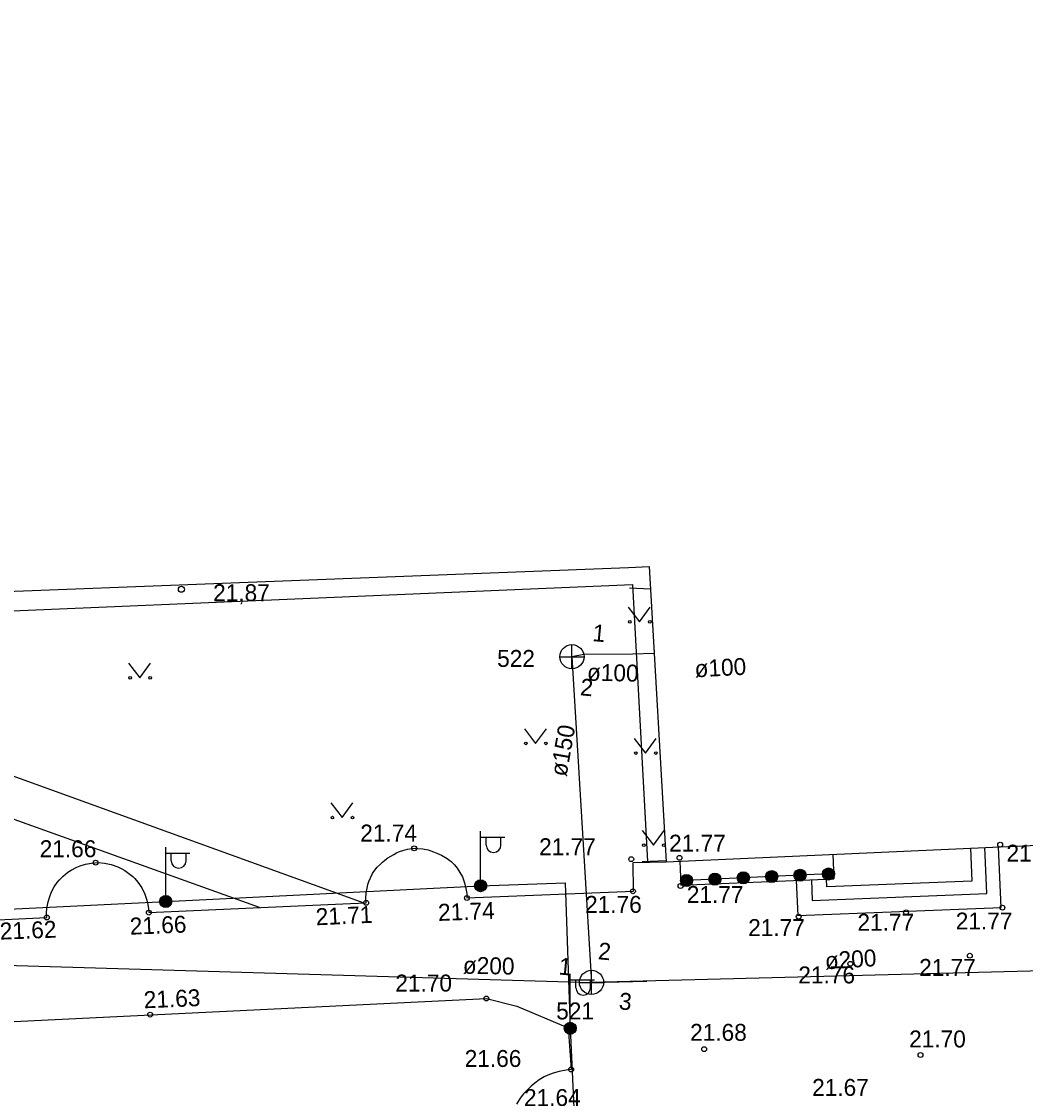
# Model space of a CAD drawing. Extents: x 714038 to 714279, y 6589845 to 6590041.
# Drawn here: x 714195.16 to 714236.66, y 6589955.84 to 6590000.35 of the extents above; entities that cross this region are included whole.
import ezdxf

# ---------------------------------------------------------------- set-up
doc = ezdxf.new("R2010")
doc.units = 0
for name, color, linetype in [('HALJASTUS', 7, 'Continuous'), ('HOONE', 7, 'Continuous'), ('HOONEDET', 7, 'Continuous'), ('KKAEV', 7, 'Continuous'), ('KORGUS', 7, 'Continuous'), ('KTRASS', 7, 'Continuous'), ('MPKAABEL', 7, 'Continuous'), ('POST', 7, 'Continuous'), ('RAJATIS', 7, 'Continuous'), ('SIKAEV', 7, 'Continuous'), ('TEE', 7, 'Continuous'), ('TORU NR', 7, 'Continuous')]:
    doc.layers.add(name, color=color, linetype=linetype)

msp = doc.modelspace()

# ---------------------------------------------------------------- linework, layer by layer
at = {"layer": 'HALJASTUS'}
for p, q in [((714220.237, 6589976.147), (714220.7, 6589975.54)), ((714220.7, 6589975.54), (714221.146, 6589976.147)), ((714199.587, 6589973.837), (714200.05, 6589973.23)), ((714200.05, 6589973.23), (714200.496, 6589973.837)), ((714215.947, 6589971.127), (714216.41, 6589970.52)), ((714216.41, 6589970.52), (714216.856, 6589971.127)), ((714220.487, 6589970.727), (714220.95, 6589970.12)), ((714220.95, 6589970.12), (714221.396, 6589970.727)), ((714207.947, 6589968.057), (714208.41, 6589967.45)), ((714208.41, 6589967.45), (714208.856, 6589968.057)), ((714220.817, 6589966.917), (714221.28, 6589966.31)), ((714221.28, 6589966.31), (714221.726, 6589966.917))]:
    msp.add_line(p, q, dxfattribs=at)
for centre in [(714220.299, 6589975.54), (714221.128, 6589975.54), (714199.649, 6589973.23), (714200.478, 6589973.23), (714216.009, 6589970.52), (714216.838, 6589970.52), (714220.549, 6589970.12), (714221.378, 6589970.12), (714208.009, 6589967.45), (714208.838, 6589967.45), (714220.879, 6589966.31), (714221.708, 6589966.31)]:
    msp.add_circle(centre, 0.055, dxfattribs=at)
at = {"layer": 'HOONE'}
msp.add_lwpolyline([(714174.151, 6590040.965), (714175.285, 6590011.657), (714176.665, 6589976.107), (714220.25, 6589977.79), (714221.11, 6589977.83), (714221.8, 6589965.63), (714240.53, 6589966.47), (714239.93, 6589984.45), (714258.589, 6589985.264), (714256.524, 6590035.954)], dxfattribs=at)
at = {"layer": 'HOONEDET'}
for points in [[(714178.211, 6589976.159), (714178.235, 6589975.468), (714180.826, 6589975.404), (714220.421, 6589977.091), (714221.034, 6589965.634)], [(714220.29, 6589976.95), (714221.16, 6589976.9)], [(714235.647, 6589963.73), (714235.543, 6589966.246)], [(714227.807, 6589964.884), (714227.843, 6589964.02), (714235.053, 6589964.31), (714234.974, 6589966.221)], [(714234.387, 6589966.194), (714234.443, 6589964.83), (714228.447, 6589964.589), (714228.434, 6589964.91)], [(714228.699, 6589965.939), (714228.734, 6589964.922)], [(714222.364, 6589965.655), (714222.417, 6589964.66)], [(714222.417, 6589964.66), (714228.734, 6589964.922)], [(714227.181, 6589964.858), (714227.242, 6589963.4)], [(714227.242, 6589963.4), (714235.647, 6589963.73)]]:
    msp.add_lwpolyline(points, dxfattribs=at)
at = {"layer": 'KKAEV'}
for p, q in [((714217.91, 6589973.6), (714217.91, 6589974.6)), ((714217.41, 6589974.1), (714218.41, 6589974.1)), ((714218.72, 6589960.14), (714218.72, 6589961.14)), ((714218.22, 6589960.64), (714219.22, 6589960.64))]:
    msp.add_line(p, q, dxfattribs=at)
for centre in [(714217.91, 6589974.1), (714218.72, 6589960.64)]:
    msp.add_circle(centre, 0.5, dxfattribs=at)
at = {"layer": 'KORGUS'}
for centre, radius in [((714201.77, 6589976.89), 0.125), ((714211.39, 6589966.18), 0.1), ((714235.61, 6589966.331), 0.1), ((714220.363, 6589965.731), 0.1), ((714222.357, 6589965.787), 0.1), ((714198.227, 6589965.587), 0.1), ((714220.433, 6589964.407), 0.1), ((714222.398, 6589964.623), 0.1), ((714209.405, 6589963.927), 0.1), ((714213.572, 6589964.13), 0.1), ((714200.424, 6589963.524), 0.1), ((714231.721, 6589963.535), 0.1), ((714235.703, 6589963.728), 0.1), ((714196.207, 6589963.323), 0.1), ((714227.284, 6589963.357), 0.1), ((714234.358, 6589961.743), 0.1), ((714229.418, 6589961.405), 0.1), ((714214.375, 6589959.974), 0.1), ((714200.481, 6589959.309), 0.1), ((714223.379, 6589957.881), 0.1), ((714232.316, 6589957.64), 0.1), ((714217.882, 6589957.042), 0.1)]:
    msp.add_circle(centre, radius, dxfattribs=at)
at = {"layer": 'KTRASS'}
for points in [[(714220.41, 6589974.2), (714218.4, 6589974.19), (714217.91, 6589974.1)], [(714217.91, 6589974.1), (714218.72, 6589960.64)], [(714221.31, 6589974.24), (714220.41, 6589974.2)], [(714172.57, 6589962.002), (714218.72, 6589960.64)], [(714246.982, 6589961.372), (714218.72, 6589960.64)], [(714218.72, 6589960.64), (714221.01, 6589960.69)]]:
    msp.add_lwpolyline(points, dxfattribs=at)
at = {"layer": 'MPKAABEL'}
msp.add_lwpolyline([(714167.029, 6589999.261), (714167.805, 6589985.535), (714167.801, 6589985.524), (714168.701, 6589969.69), (714168.856, 6589964.517), (714181.003, 6589963.765), (714182.873, 6589963.649), (714187.834, 6589963.342), (714201.122, 6589963.986), (714214.138, 6589964.636), (714217.634, 6589964.759), (714217.843, 6589958.743), (714218.335, 6589947.958), (714218.782, 6589937.076), (714219.871, 6589937.206), (714226.57, 6589937.936), (714228.214, 6589938.132), (714236.763, 6589938.683), (714246.845, 6589940.926), (714247.938, 6589921.303)], dxfattribs=at)
at = {"layer": 'POST'}
for p, q in [((714214.138, 6589964.886), (714214.138, 6589966.886)), ((714201.122, 6589964.236), (714201.122, 6589966.236)), ((714214.138, 6589966.636), (714215.138, 6589966.636)), ((714214.365, 6589966.315), (714214.365, 6589966.636)), ((714214.977, 6589966.315), (714214.977, 6589966.636)), ((714201.122, 6589965.986), (714202.122, 6589965.986)), ((714201.349, 6589965.665), (714201.349, 6589965.986)), ((714201.961, 6589965.665), (714201.961, 6589965.986)), ((714217.843, 6589958.993), (714217.843, 6589960.993)), ((714217.843, 6589960.743), (714218.843, 6589960.743)), ((714218.07, 6589960.422), (714218.07, 6589960.743)), ((714218.682, 6589960.422), (714218.682, 6589960.743))]:
    msp.add_line(p, q, dxfattribs=at)
for centre, radius in [((714214.138, 6589964.636), 0.25), ((714214.138, 6589964.636), 0.225), ((714214.138, 6589964.636), 0.2), ((714214.138, 6589964.636), 0.175), ((714214.138, 6589964.636), 0.15), ((714214.138, 6589964.636), 0.125), ((714214.138, 6589964.636), 0.1), ((714214.138, 6589964.636), 0.075), ((714214.138, 6589964.636), 0.05), ((714214.138, 6589964.636), 0.025), ((714201.122, 6589963.986), 0.25), ((714201.122, 6589963.986), 0.225), ((714201.122, 6589963.986), 0.2), ((714201.122, 6589963.986), 0.175), ((714201.122, 6589963.986), 0.15), ((714201.122, 6589963.986), 0.125), ((714201.122, 6589963.986), 0.1), ((714201.122, 6589963.986), 0.075), ((714201.122, 6589963.986), 0.05), ((714201.122, 6589963.986), 0.025), ((714217.843, 6589958.743), 0.25), ((714217.843, 6589958.743), 0.225), ((714217.843, 6589958.743), 0.2), ((714217.843, 6589958.743), 0.175), ((714217.843, 6589958.743), 0.15), ((714217.843, 6589958.743), 0.125), ((714217.843, 6589958.743), 0.1), ((714217.843, 6589958.743), 0.075), ((714217.843, 6589958.743), 0.05), ((714217.843, 6589958.743), 0.025)]:
    msp.add_circle(centre, radius, dxfattribs=at)
for centre in [(714214.671, 6589966.315), (714201.655, 6589965.665), (714218.376, 6589960.422)]:
    msp.add_arc(centre, 0.306, 180, 0, dxfattribs=at)
at = {"layer": 'RAJATIS'}
for centre, radius in [((714228.512, 6589965.122), 0.25), ((714228.512, 6589965.122), 0.225), ((714222.65, 6589964.85), 0.25), ((714222.65, 6589964.85), 0.225), ((714222.65, 6589964.85), 0.2), ((714222.65, 6589964.85), 0.175), ((714222.65, 6589964.85), 0.15), ((714222.65, 6589964.85), 0.125), ((714222.65, 6589964.85), 0.1), ((714222.65, 6589964.85), 0.075), ((714222.65, 6589964.85), 0.05), ((714223.822, 6589964.905), 0.25), ((714223.822, 6589964.905), 0.225), ((714223.822, 6589964.905), 0.2), ((714223.822, 6589964.905), 0.175), ((714223.822, 6589964.905), 0.15), ((714223.822, 6589964.905), 0.125), ((714223.822, 6589964.905), 0.1), ((714223.822, 6589964.905), 0.075), ((714223.822, 6589964.905), 0.05), ((714223.822, 6589964.905), 0.025), ((714224.995, 6589964.959), 0.25), ((714224.995, 6589964.959), 0.225), ((714224.995, 6589964.959), 0.2), ((714224.995, 6589964.959), 0.175), ((714224.995, 6589964.959), 0.15), ((714224.995, 6589964.959), 0.125), ((714224.995, 6589964.959), 0.1), ((714224.995, 6589964.959), 0.075), ((714224.995, 6589964.959), 0.05), ((714224.995, 6589964.959), 0.025), ((714226.167, 6589965.013), 0.25), ((714226.167, 6589965.013), 0.225), ((714226.167, 6589965.013), 0.2), ((714226.167, 6589965.013), 0.175), ((714226.167, 6589965.013), 0.15), ((714226.167, 6589965.013), 0.125), ((714226.167, 6589965.013), 0.1), ((714226.167, 6589965.013), 0.075), ((714226.167, 6589965.013), 0.05), ((714226.167, 6589965.013), 0.025), ((714227.339, 6589965.068), 0.25), ((714227.339, 6589965.068), 0.225), ((714227.339, 6589965.068), 0.2), ((714227.339, 6589965.068), 0.175), ((714227.339, 6589965.068), 0.15), ((714227.339, 6589965.068), 0.125), ((714227.339, 6589965.068), 0.1), ((714227.339, 6589965.068), 0.075), ((714227.339, 6589965.068), 0.05), ((714227.339, 6589965.068), 0.025), ((714228.512, 6589965.122), 0.2), ((714228.512, 6589965.122), 0.175), ((714228.512, 6589965.122), 0.15), ((714228.512, 6589965.122), 0.125), ((714228.512, 6589965.122), 0.1), ((714228.512, 6589965.122), 0.075), ((714228.512, 6589965.122), 0.05), ((714228.512, 6589965.122), 0.025), ((714222.65, 6589964.85), 0.025)]:
    msp.add_circle(centre, radius, dxfattribs=at)
at = {"layer": 'TEE'}
for points in [[(714175.406, 6589976.189), (714209.316, 6589963.923)], [(714204.994, 6589963.729), (714175.489, 6589974.311)], [(714187.217, 6589962.898), (714196.207, 6589963.323), (714196.202, 6589963.428), (714196.202, 6589963.532), (714196.211, 6589963.682), (714196.231, 6589963.829), (714196.261, 6589963.976), (714196.327, 6589964.196), (714196.407, 6589964.386), (714196.518, 6589964.589), (714196.641, 6589964.766), (714196.737, 6589964.883), (714196.88, 6589965.028), (714197.079, 6589965.191), (714197.214, 6589965.28), (714197.45, 6589965.404), (714197.587, 6589965.46), (714197.812, 6589965.529), (714198.051, 6589965.572), (714198.332, 6589965.589), (714198.589, 6589965.571), (714198.873, 6589965.513), (714199.145, 6589965.418), (714199.314, 6589965.336), (714199.438, 6589965.264), (714199.758, 6589965.016), (714199.845, 6589964.931), (714199.974, 6589964.781), (714200.13, 6589964.552), (714200.264, 6589964.284), (714200.347, 6589964.044), (714200.39, 6589963.855), (714200.414, 6589963.684), (714200.424, 6589963.524), (714208.44, 6589963.884), (714209.405, 6589963.927), (714209.399, 6589964.102), (714209.412, 6589964.341), (714209.443, 6589964.54), (714209.476, 6589964.683), (714209.513, 6589964.808), (714209.664, 6589965.14), (714209.719, 6589965.225), (714209.86, 6589965.4), (714210.009, 6589965.547), (714210.083, 6589965.611), (714210.183, 6589965.691), (714210.308, 6589965.783), (714210.548, 6589965.931), (714210.659, 6589965.989), (714210.786, 6589966.046), (714210.919, 6589966.094), (714211.112, 6589966.145), (714211.288, 6589966.172), (714211.437, 6589966.182), (714211.548, 6589966.181), (714211.754, 6589966.162), (714211.964, 6589966.118), (714212.191, 6589966.043), (714212.326, 6589965.988), (714212.522, 6589965.894), (714212.756, 6589965.756), (714212.917, 6589965.636), (714213.061, 6589965.5), (714213.174, 6589965.366), (714213.385, 6589965), (714213.474, 6589964.759), (714213.533, 6589964.521), (714213.562, 6589964.321), (714213.572, 6589964.13), (714220.462, 6589964.408), (714220.443, 6589965.59), (714221.8, 6589965.63)], [(714221.8, 6589965.66), (714220.81, 6589965.63)], [(714228.512, 6589965.122), (714222.65, 6589964.85)], [(714181.822, 6589958.396), (714214.375, 6589959.974), (714215.636, 6589959.658), (714217.66, 6589958.805), (714217.765, 6589958.58), (714217.882, 6589957.042), (714217.679, 6589957.018), (714217.384, 6589956.96), (714217.139, 6589956.889), (714216.914, 6589956.805), (714216.76, 6589956.732), (714216.562, 6589956.617), (714216.372, 6589956.48), (714216.225, 6589956.352), (714216.016, 6589956.142), (714215.916, 6589956.028), (714215.778, 6589955.853), (714215.614, 6589955.612)]]:
    msp.add_lwpolyline(points, dxfattribs=at)

# ---------------------------------------------------------------- texts
at = {"layer": 'KORGUS'}
for s, p in [('21,87', (714203.081, 6589976.395)), (' 21.74 ', (714208.902, 6589966.463)), (' 21.77', (714221.666, 6589966.044)), (' 21.66', (714195.654, 6589965.815)), (' 21.77', (714216.294, 6589965.897)), (' 21.77', (714235.61, 6589965.631)), (' 21.77', (714222.398, 6589963.923)), (' 21.76', (714218.194, 6589963.515)), (' 21.77', (714224.935, 6589962.555)), (' 21.77 ', (714229.451, 6589962.774)), (' 21.77', (714233.514, 6589962.827)), (' 21.77', (714232.002, 6589960.909)), (' 21.70', (714210.352, 6589960.263)), (' 21.76', (714227.008, 6589960.598)), (' 21.68 ', (714222.535, 6589958.225)), (' 21.70', (714231.588, 6589957.952)), (' 21.66', (714213.22, 6589957.145)), (' 21.67', (714227.579, 6589955.95)), (' 21.64', (714215.671, 6589955.53))]:
    msp.add_text(s, height=0.7, dxfattribs=at).set_placement(p)
for s, rotation, p in [(' 21.71', 2.5817, (714207.079, 6589962.987)), (' 21.74', 2.0464, (714212.13, 6589963.17)), (' 21.62', 2.0486, (714194.017, 6589962.398)), (' 21.66', 2.2711, (714199.391, 6589962.6)), (' 21.63', 2.3485, (714199.968, 6589959.558))]:
    msp.add_text(s, height=0.7, rotation=rotation, dxfattribs=at).set_placement(p)
at = {"layer": 'SIKAEV'}
for s, p in [('522', (714214.82, 6589973.68)), ('521', (714217.26, 6589959.11))]:
    msp.add_text(s, height=0.7, dxfattribs=at).set_placement(p)
at = {"layer": 'TORU NR'}
for s, rotation, p in [('1', 354.7103, (714218.741, 6589974.75)), ('ø100', 358.8423, (714218.528, 6589973.111)), ('ø100', 2.9564, (714222.998, 6589973.247)), ('2', 354.7103, (714218.231, 6589972.51)), ('ø150', 79.9901, (714217.682, 6589969.116)), ('2', 354.7103, (714218.971, 6589961.6)), ('ø200', 3.7987, (714228.387, 6589961.175)), ('ø200', 358.8423, (714213.398, 6589961.002)), ('1', 354.7103, (714217.341, 6589960.97)), ('3', 354.7103, (714219.831, 6589959.53))]:
    msp.add_text(s, height=0.7, rotation=rotation, dxfattribs=at).set_placement(p)

doc.saveas('drawing.dxf')
